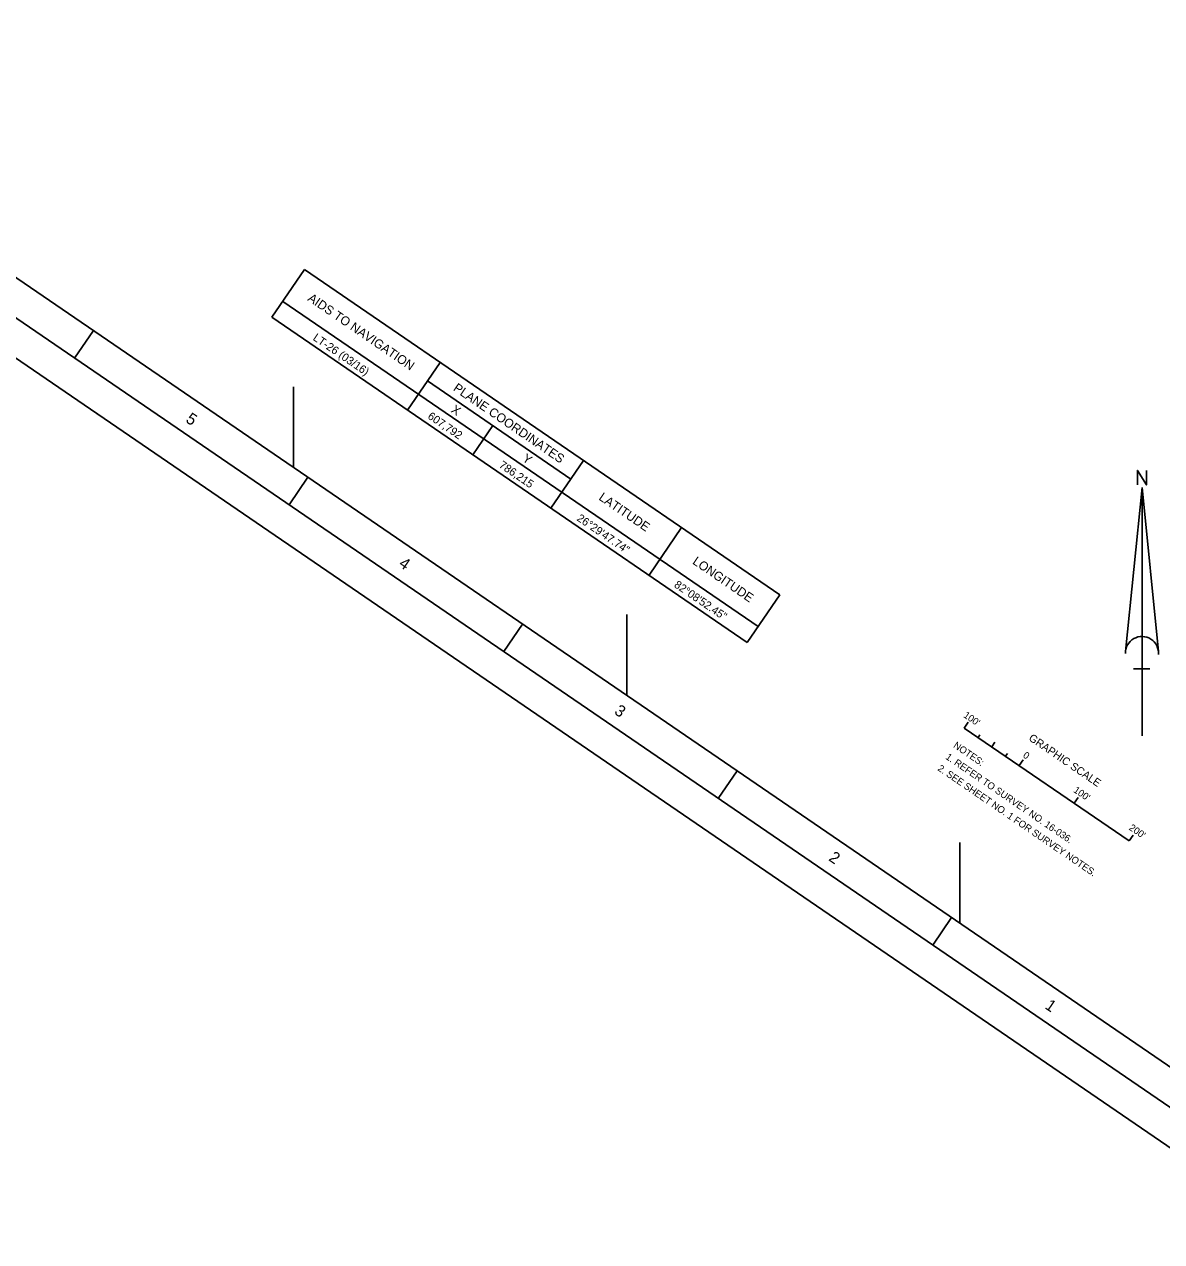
# Model space of a CAD drawing. Extents: x 605889 to 611440, y 782978 to 788269.
# Drawn here: x 607596 to 609303, y 782979 to 784804 of the extents above; entities that cross this region are included whole.
import ezdxf

# ---------------------------------------------------------------- set-up
doc = ezdxf.new("R2010")
doc.units = 0
for name, color, linetype in [('G-ANNO-NPLT', 7, 'Continuous'), ('G-ANNO-TTLB', 7, 'Continuous'), ('V-ANNO-NOTE', 7, 'Continuous'), ('V-ANNO-SCHD', 7, 'Continuous'), ('V-ANNO-SYMB', 7, 'Continuous'), ('V-TOPO-COOR-STAT', 7, 'Continuous')]:
    doc.layers.add(name, color=color, linetype=linetype)

msp = doc.modelspace()

# ---------------------------------------------------------------- linework, layer by layer
at = {"layer": 'G-ANNO-NPLT'}
msp.add_lwpolyline([(607807.9, 788268.5), (611440.1, 785785.2), (609521.2, 782978.5), (605889, 785461.8)], close=True, dxfattribs=at)
at = {"layer": 'G-ANNO-TTLB'}
for p, q in [((607671.4, 784303.8), (607699.6, 784345)), ((607993.3, 784083.7), (608021.6, 784124.9)), ((608315.3, 783863.5), (608343.5, 783904.8)), ((608637.2, 783643.4), (608665.5, 783684.7)), ((608959.2, 783423.3), (608987.4, 783464.6))]:
    msp.add_line(p, q, dxfattribs=at)
for points in [[(605958.5, 785474.9), (609508.1, 783048), (611370.6, 785772.2), (607821, 788199)], [(611301.1, 785759.1), (607895.9, 788087.2), (606089.9, 785445.6), (609495.1, 783117.5)]]:
    msp.add_lwpolyline(points, close=True, dxfattribs=at)
at = {"layer": 'V-ANNO-NOTE'}
for p, q in [((609006.6, 783748.9), (609012.5, 783757.6)), ((609006.6, 783748.9), (609254.2, 783579.6)), ((609027.2, 783734.8), (609029.9, 783738.8)), ((609047.8, 783720.7), (609052.6, 783727.8)), ((609068.5, 783706.6), (609071.2, 783710.6)), ((609089.1, 783692.5), (609095, 783701.1)), ((609089.1, 783692.5), (609095, 783701.1)), ((609089.1, 783692.5), (609091.9, 783696.6)), ((609171.7, 783636.1), (609177.6, 783644.7)), ((609254.2, 783579.6), (609260.1, 783588.2))]:
    msp.add_line(p, q, dxfattribs=at)
at = {"layer": 'V-ANNO-SCHD'}
for p, q in [((608016.3, 784436.5), (607967.4, 784365)), ((608016.3, 784436.5), (608729.6, 783948.8)), ((607983.7, 784388.8), (608697, 783901.2)), ((607967.4, 784365), (608680.7, 783877.4)), ((608219.9, 784297.3), (608171, 784225.8)), ((608200.9, 784269.5), (608416.1, 784122.3)), ((608299, 784202.4), (608269.2, 784158.7)), ((608435.1, 784150.1), (608386.2, 784078.7)), ((608582.3, 784049.5), (608533.5, 783978)), ((608680.7, 783877.4), (608729.6, 783948.8))]:
    msp.add_line(p, q, dxfattribs=at)
at = {"layer": 'V-ANNO-SYMB'}
for p, q in [((609248.6, 783863.9), (609273.3, 784109.6)), ((609273.3, 783737.3), (609273.3, 784109.6)), ((609298, 783863.9), (609273.3, 784109.6)), ((609285.1, 783837.8), (609260.3, 783837.8))]:
    msp.add_line(p, q, dxfattribs=at)
msp.add_lwpolyline([(609266.5, 784113.6), (609266.5, 784135.3), (609280, 784113.6), (609280, 784135.3)], dxfattribs=at)
msp.add_arc((609273.3, 783861.4), 24.8, 355.2984, 182.0673, dxfattribs=at)
at = {"layer": 'V-TOPO-COOR-STAT'}
for p, q in [((608000, 784139.7), (608000, 784260.8)), ((608500, 783797.8), (608500, 783919)), ((609000, 783456), (609000, 783577.1))]:
    msp.add_line(p, q, dxfattribs=at)

# ---------------------------------------------------------------- texts
at = {"layer": 'G-ANNO-TTLB'}
for s, p in [('5', (607836.8, 784208.8)), ('4', (608156.6, 783992.2)), ('3', (608480, 783771.1)), ('2', (608801.8, 783551.1)), ('1', (609126.3, 783329.2))]:
    msp.add_text(s, height=17.5, rotation=325.6398, dxfattribs=at).set_placement(p)
at = {"layer": 'V-ANNO-NOTE'}
for s, height, p in [("100'", 10.42, (609004.4, 783765.8)), ('GRAPHIC SCALE', 11.666, (609102.2, 783731.4)), ('NOTES:', 10.42, (608989.2, 783720.5)), ('0', 10.4, (609093.6, 783705.7)), ('2. SEE SHEET NO. 1 FOR SURVEY NOTES.', 10.416, (608965.7, 783686.1)), ('1. REFER TO SURVEY NO. 16-036.', 10.416, (608977.5, 783703.3)), ("100'", 10.42, (609169.5, 783653.5)), ("200'", 10.42, (609252.8, 783597.1))]:
    msp.add_text(s, height=height, rotation=325.6398, dxfattribs=at).set_placement(p)
at = {"layer": 'V-ANNO-SCHD'}
for s, height, p in [('AIDS TO NAVIGATION', 13.471, (608020.1, 784390.8)), ('PLANE COORDINATES', 13.471, (608238.5, 784256)), ('X', 13.5, (608235, 784223.5)), ('Y', 13.5, (608342.1, 784150.2)), ('LATITUDE', 13.47, (608456.9, 784092.1)), ('LONGITUDE', 13.47, (608597.6, 783996))]:
    msp.add_text(s, height=height, rotation=325.6398, dxfattribs=at).set_placement(p)
at = {"layer": 'V-ANNO-SYMB'}
for s, p in [('LT-26 (03/16)', (608028, 784331.7)), ('607,792', (608200.2, 784214)), ('786,215', (608307.2, 784140.8)), ('26%%D29\'47.74"', (608424, 784061)), ('82%%D08\'52.45"', (608570, 783961.2))]:
    msp.add_text(s, height=12, rotation=325.6398, dxfattribs=at).set_placement(p)

doc.saveas('drawing.dxf')
